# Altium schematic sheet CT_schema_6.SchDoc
size 218 x 258 mm
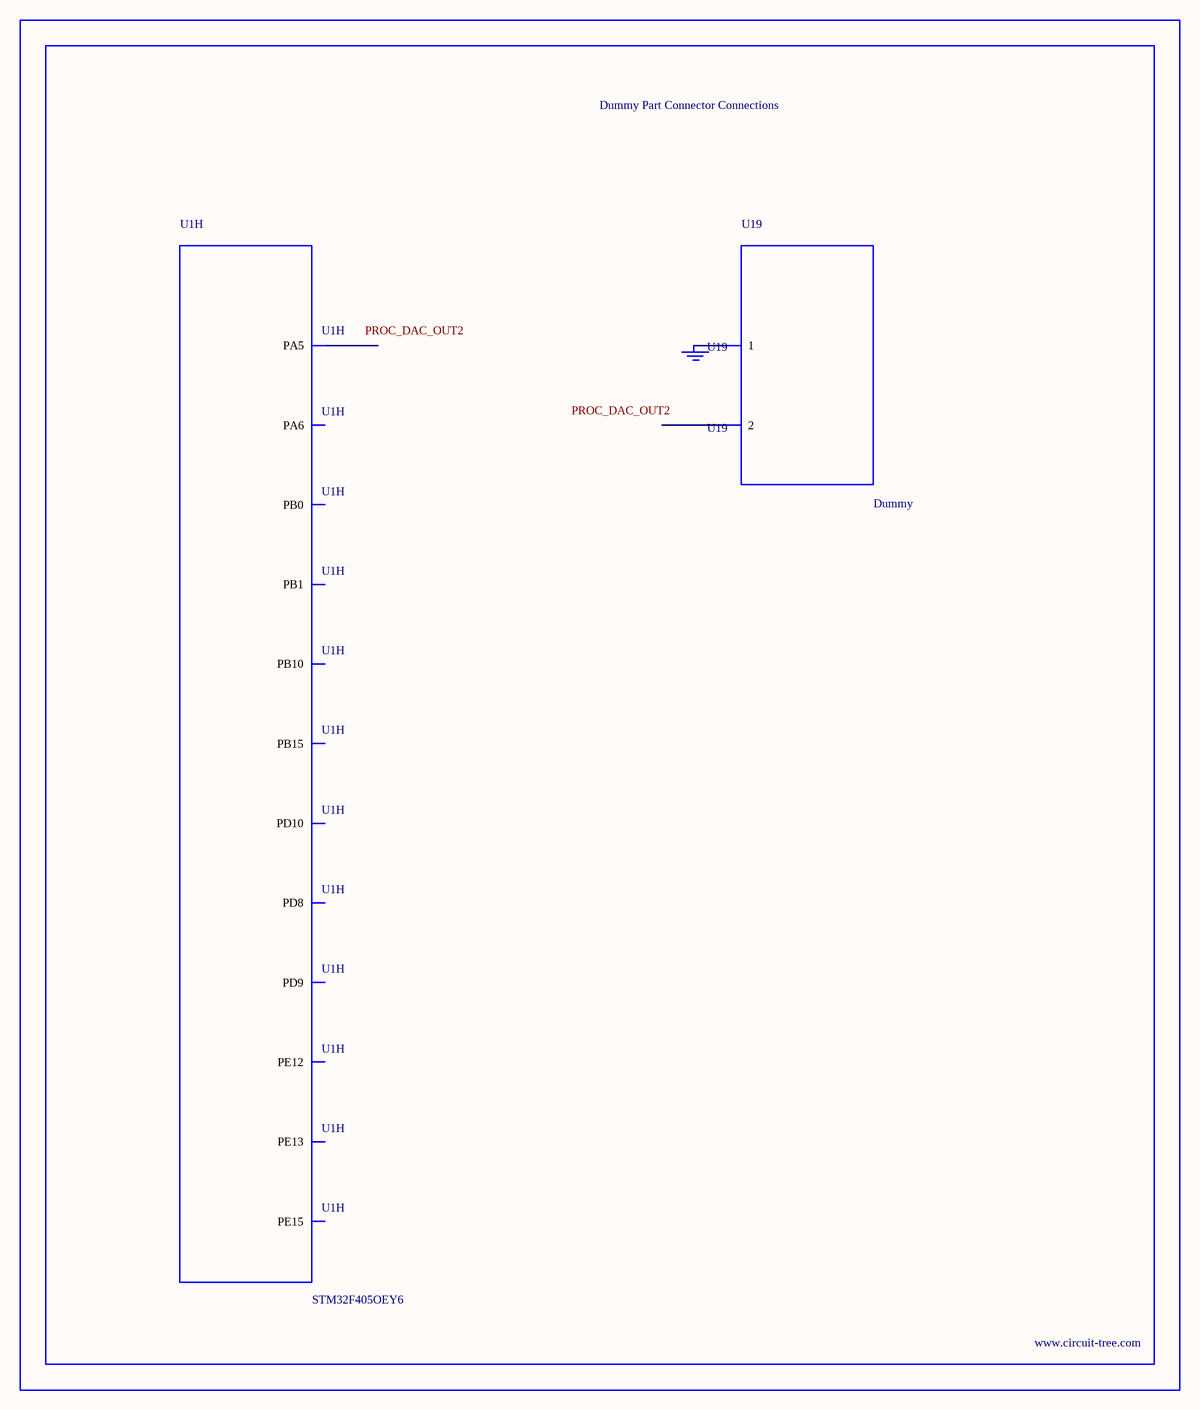
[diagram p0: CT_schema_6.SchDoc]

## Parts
BORDER5  (no value)
GND_INSTANCE_5_0  (no value)
U1  STM32F405OEY6  [WLCSP90]  (part H of 8)
U19  Dummy  [DUMMY_PACKAGE_230]

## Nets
NetGND_INSTANCE_5_0_0: GND_INSTANCE_5_0.0(GND) U19.1

Not connected (* = marked no-connect by the designer): U1 G3(PD10) G4(PE15) G5(PE13) G7(PB0) G8(PA5) H1(PB15) H2(PD8) H3(PD9) H4(PB10) H5(PE12) H7(PB1) H8(PA6); U19 2

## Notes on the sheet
- Labels drawn without touching a wire or pin: PROC_DAC_OUT2

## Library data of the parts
BORDER5 = BORDER_PAGE5
GND_INSTANCE_5_0 = GND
